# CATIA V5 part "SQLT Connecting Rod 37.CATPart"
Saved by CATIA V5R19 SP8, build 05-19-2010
Part number: SQLT Connecting Rod 37
Publications: "Droite.1", "Plan.1", "Plan.2", "Droite.2", "Droite.3", "Plan.3", "Plan.4", "Plan.5", "Plan.6", "Point.3"
Bounding box of the stored display mesh (mm): x -150 to 150, y 580 to 680, z 500 to 605
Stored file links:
  G:\EU_thinkMotion\CFAO_2010\MMS_groupe3\MMS_groupe3\A reprendre\fovide\fovide\SQLT Connecting Rod 37.CATPart
  G:\EU_thinkMotion\CFAO_2010\MMS_groupe3\MMS_groupe3\A reprendre\fovide\fovide\fovide.CATProduct
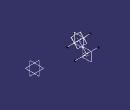
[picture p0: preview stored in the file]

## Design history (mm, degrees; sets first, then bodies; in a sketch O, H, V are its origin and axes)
Set1
  Point1 "Point.L": linked copy from another document
  Point2 "Point.M": linked copy from another document
Set2 "set Connecting Rod 37"
  Line1: type PtPt, FirstPoint Point1, SecondPoint Point2
  Plane1: type OffsetPt, RefPlane yz-plane, RefPoint Point1
  Plane2: type OffsetPt, RefPlane yz-plane, RefPoint Point2
  Line2: type Normal, RefPoint Point2, RefSkin Plane2, Start -150, End 150
  Line3: type Normal, RefPoint Point1, RefSkin Plane1, Start -150, End 150
  Plane3: type Normal, Curve Line1, RefPoint Point2
  Plane4: type Angle, RefPlane Plane3, Direction Line2, Angle 90
  Plane5: type Offset, RefPlane Plane4, Offset 2
  Plane6: type Offset, RefPlane Plane4, Offset 2, reversed
  Point3: type OnCurve, Support Line3, Length 132
Body1 (main body)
